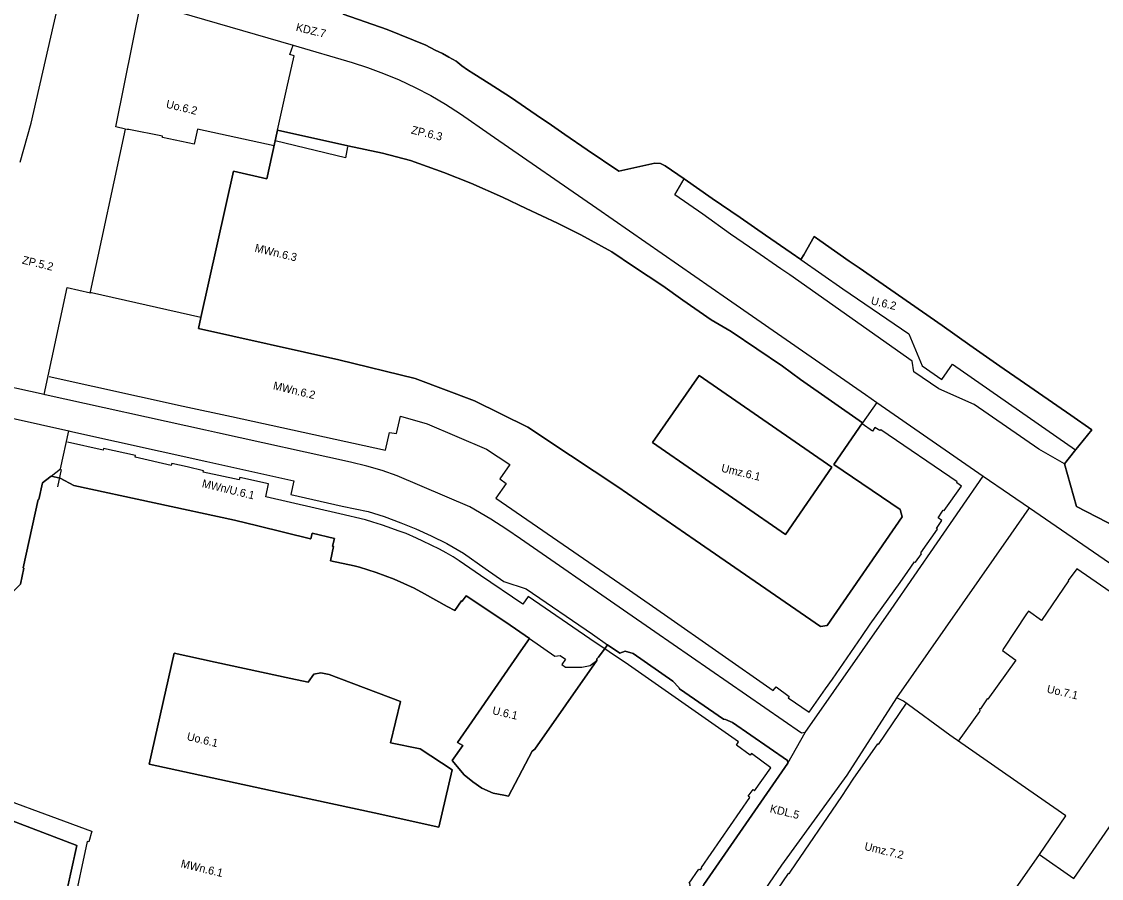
# Model space of a CAD drawing. Extents: x 7429686 to 7432896, y 5547954 to 5550600.
# Drawn here: x 7431331 to 7431871, y 5549657 to 5550085 of the extents above; entities that cross this region are included whole.
import ezdxf

# ---------------------------------------------------------------- set-up
doc = ezdxf.new("R2010")
doc.units = 0
for name, color, linetype in [('granica planu', 7, 'Continuous'), ('linie rozgraniczające', 7, 'Continuous'), ('nieprzekraczalna linia zabudowy', 7, 'Continuous'), ('obowiązująca linia zabudowy', 7, 'Continuous'), ('oznaczenia przeznaczeń', 7, 'Continuous')]:
    doc.layers.add(name, color=color, linetype=linetype)

msp = doc.modelspace()

# ---------------------------------------------------------------- linework, layer by layer
at = {"layer": 'granica planu'}
msp.add_lwpolyline([(7431492.16, 5550088.86), (7431514.08, 5550081.13), (7431533.41, 5550073.41), (7431538.07, 5550070.86), (7431541.78, 5550069.16), (7431544.95, 5550067.39), (7431548.55, 5550065.42), (7431549.45, 5550064.68), (7431551.38, 5550063.11), (7431554.34, 5550061.11), (7431557.5, 5550059.12), (7431565.17, 5550054.17), (7431575.82, 5550047.31), (7431588.58, 5550038.53), (7431596.17, 5550033.34), (7431602.99, 5550028.7), (7431614.12, 5550021.1), (7431629.82, 5550010.4), (7431647.84, 5550014.36), (7431650.74, 5550014.23), (7431653.1, 5550013.01), (7431662.53, 5550006.51), (7431676.53, 5549996.85), (7431690.53, 5549987.2), (7431703.2, 5549978.48), (7431716.01, 5549969.64), (7431720.86, 5549966.3), (7431722.24, 5549968.65), (7431727.56, 5549977.72), (7431730.29, 5549975.84), (7431745.04, 5549965.53), (7431749.96, 5549962.11), (7431791.39, 5549933.25), (7431805.34, 5549923.53), (7431820.33, 5549913.08), (7431822.49, 5549911.58), (7431830.37, 5549906.09), (7431855.65, 5549888.47), (7431866.16, 5549881.15), (7431857.58, 5549870.55), (7431852.56, 5549864.15), (7431858.59, 5549842.92), (7431955.59, 5549792.81)], dxfattribs=at)
at = {"layer": 'linie rozgraniczające'}
for p, q in [((7431459.36, 5550030.98), (7431453.98, 5550006.65)), ((7431494.51, 5550023.03), (7431459.36, 5550030.98)), ((7431511.89, 5550019.45), (7431494.51, 5550023.03)), ((7431525.8, 5550015.74), (7431511.89, 5550019.45)), ((7431542.43, 5550009.76), (7431525.8, 5550015.74)), ((7431556, 5550004.5), (7431542.43, 5550009.76)), ((7431571.74, 5549997.36), (7431556, 5550004.5)), ((7431583.66, 5549991.85), (7431571.74, 5549997.36)), ((7431599.28, 5549984.47), (7431583.66, 5549991.85)), ((7431610.82, 5549978.54), (7431599.28, 5549984.47)), ((7431626.4, 5549970.11), (7431610.82, 5549978.54)), ((7431637.21, 5549962.76), (7431626.4, 5549970.11)), ((7431651.88, 5549953.12), (7431637.21, 5549962.76)), ((7431661.83, 5549945.98), (7431651.88, 5549953.12)), ((7431676.03, 5549936.21), (7431661.83, 5549945.98)), ((7431686.08, 5549930.37), (7431676.03, 5549936.21)), ((7431711.66, 5549913.01), (7431686.08, 5549930.37)), ((7431720.63, 5549906.35), (7431711.66, 5549913.01)), ((7431736.35, 5549862.5), (7431670.09, 5549908.37)), ((7431670.09, 5549908.37), (7431736.35, 5549862.5)), ((7431751.68, 5549884.66), (7431720.63, 5549906.35)), ((7431557.81, 5549895.77), (7431584.5, 5549882.55)), ((7431737.32, 5549863.9), (7431751.68, 5549884.66)), ((7431713.11, 5549828.92), (7431736.35, 5549862.5)), ((7431736.35, 5549862.5), (7431713.11, 5549828.92)), ((7431770.41, 5549841.48), (7431737.32, 5549863.9)), ((7431341.93, 5549854.71), (7431340.14, 5549846.42)), ((7431345.63, 5549857.59), (7431341.93, 5549854.71)), ((7431346.28, 5549858.1), (7431345.63, 5549857.59)), ((7431629.36, 5549852.79), (7431668.05, 5549826.1)), ((7431339.7, 5549846.45), (7431332.2, 5549812.2)), ((7431340.14, 5549846.42), (7431339.7, 5549846.45)), ((7431771.49, 5549837.73), (7431770.41, 5549841.48)), ((7431476.68, 5549829.61), (7431476.17, 5549827.35)), ((7431487.81, 5549826.91), (7431476.68, 5549829.61)), ((7431485.75, 5549815.81), (7431487.35, 5549822.97)), ((7431668.05, 5549826.1), (7431730.64, 5549782.92)), ((7431332.59, 5549812.04), (7431330.89, 5549804.16)), ((7431332.2, 5549812.2), (7431332.59, 5549812.04)), ((7431585.18, 5549776.95), (7431573.48, 5549785.17)), ((7431618.88, 5549765.93), (7431587.91, 5549721.73)), ((7431546.55, 5549711.43), (7431530.66, 5549721.85)), ((7431530.66, 5549721.85), (7431546.55, 5549711.43)), ((7431672.28, 5549654.05), (7431714.41, 5549714.66)), ((7431300.13, 5549695.97), (7431359.15, 5549673.6)), ((7431359.15, 5549673.6), (7431350.69, 5549635.72))]:
    msp.add_line(p, q, dxfattribs=at)
for points in [[(7431336.35, 5550034.33), (7431351.87, 5550103.07)], [(7431378.63, 5550032.55), (7431391.27, 5550095.33)], [(7431391.27, 5550095.33), (7431467.17, 5550073.29)], [(7431662.53, 5550006.51), (7431653.1, 5550013.01), (7431650.74, 5550014.23), (7431647.84, 5550014.36), (7431629.82, 5550010.4), (7431614.12, 5550021.1), (7431602.99, 5550028.7), (7431596.17, 5550033.34), (7431588.58, 5550038.53), (7431575.82, 5550047.31), (7431565.17, 5550054.17), (7431557.5, 5550059.12), (7431554.34, 5550061.11), (7431551.38, 5550063.11), (7431549.45, 5550064.68), (7431548.55, 5550065.42), (7431544.95, 5550067.39), (7431541.78, 5550069.16), (7431538.07, 5550070.86), (7431533.41, 5550073.41), (7431514.08, 5550081.13), (7431492.16, 5550088.86)], [(7431465.55, 5550068.63), (7431467.17, 5550073.29)], [(7431467.17, 5550073.29), (7431496.63, 5550064.73)], [(7431463.98, 5550051.88), (7431467.59, 5550068.09)], [(7431467.59, 5550068.09), (7431465.55, 5550068.63)], [(7431496.63, 5550064.73), (7431504.34, 5550062.24)], [(7431504.34, 5550062.24), (7431512.37, 5550059.22)], [(7431512.37, 5550059.22), (7431520.14, 5550056.01)], [(7431520.14, 5550056.01), (7431528.16, 5550052.26)], [(7431459.66, 5550032.33), (7431463.98, 5550051.88)], [(7431528.16, 5550052.26), (7431535.91, 5550048.26)], [(7431535.91, 5550048.26), (7431543.34, 5550043.87)], [(7431543.34, 5550043.87), (7431550.72, 5550039.02)], [(7431550.72, 5550039.02), (7431565.67, 5550028.68)], [(7431330.83, 5550014.86), (7431336.35, 5550034.33)], [(7431365.98, 5549950.18), (7431383.4, 5550031.42)], [(7431383.4, 5550031.42), (7431378.63, 5550032.55)], [(7431459.36, 5550030.98), (7431459.66, 5550032.33)], [(7431421.01, 5549937.29), (7431437.36, 5550010.38), (7431453.98, 5550006.65), (7431459.36, 5550030.98)], [(7431459.36, 5550030.98), (7431494.51, 5550023.03), (7431511.89, 5550019.45), (7431525.8, 5550015.74), (7431542.43, 5550009.76), (7431556, 5550004.5), (7431571.74, 5549997.36), (7431583.66, 5549991.85), (7431599.28, 5549984.47), (7431610.82, 5549978.54), (7431626.4, 5549970.11), (7431637.21, 5549962.76), (7431651.88, 5549953.12), (7431661.83, 5549945.98), (7431676.03, 5549936.21), (7431686.08, 5549930.37), (7431711.66, 5549913.01), (7431720.63, 5549906.35), (7431751.68, 5549884.66)], [(7431565.67, 5550028.68), (7431567.72, 5550027.26)], [(7431567.72, 5550027.26), (7431618.83, 5549991.92)], [(7431453.98, 5550006.65), (7431437.36, 5550010.38), (7431421.01, 5549937.29)], [(7431657.92, 5549998.63), (7431662.53, 5550006.51)], [(7431852.56, 5549864.15), (7431857.58, 5549870.55), (7431866.16, 5549881.15), (7431855.65, 5549888.47), (7431830.37, 5549906.09), (7431822.49, 5549911.58), (7431820.33, 5549913.08), (7431805.34, 5549923.53), (7431791.39, 5549933.25), (7431749.96, 5549962.11), (7431745.04, 5549965.53), (7431730.29, 5549975.84), (7431727.56, 5549977.72), (7431722.24, 5549968.65), (7431720.86, 5549966.3), (7431716.01, 5549969.64), (7431703.2, 5549978.48), (7431690.53, 5549987.2), (7431676.53, 5549996.85), (7431662.53, 5550006.51)], [(7431671.92, 5549988.91), (7431657.92, 5549998.63)], [(7431618.83, 5549991.92), (7431684.1, 5549946.63)], [(7431685.75, 5549978.97), (7431671.92, 5549988.91)], [(7431698.41, 5549970.24), (7431685.75, 5549978.97)], [(7431710.77, 5549961.71), (7431698.41, 5549970.24)], [(7431715.3, 5549958.58), (7431710.77, 5549961.71)], [(7431776.51, 5549915.59), (7431715.3, 5549958.58)], [(7431342.73, 5549898.88), (7431354.21, 5549952.32)], [(7431354.21, 5549952.32), (7431365.87, 5549949.69)], [(7431365.87, 5549949.69), (7431365.98, 5549950.18)], [(7431366.36, 5549949.58), (7431365.87, 5549949.69)], [(7431421.01, 5549937.29), (7431366.36, 5549949.58)], [(7431684.1, 5549946.63), (7431753.19, 5549898.78)], [(7431421.01, 5549937.29), (7431419.81, 5549931.9), (7431490.03, 5549916.19), (7431528.06, 5549906.78), (7431557.81, 5549895.77)], [(7431751.68, 5549884.66), (7431737.32, 5549863.9), (7431770.41, 5549841.48), (7431771.49, 5549837.73), (7431734.02, 5549783.54), (7431730.64, 5549782.92), (7431668.05, 5549826.1), (7431629.36, 5549852.79), (7431605.72, 5549868.47), (7431584.5, 5549882.55), (7431557.81, 5549895.77), (7431528.06, 5549906.78), (7431490.03, 5549916.19), (7431419.81, 5549931.9), (7431421.01, 5549937.29)], [(7431777.3, 5549910.17), (7431776.51, 5549915.59)], [(7431670.09, 5549908.37), (7431646.77, 5549874.81), (7431713.11, 5549828.92)], [(7431713.11, 5549828.92), (7431646.77, 5549874.81), (7431670.09, 5549908.37)], [(7431789.82, 5549901.66), (7431777.3, 5549910.17)], [(7431342.73, 5549898.88), (7431313.84, 5549905.24)], [(7431343.22, 5549898.77), (7431342.73, 5549898.88)], [(7431423.43, 5549881.09), (7431343.22, 5549898.77)], [(7431753.19, 5549898.78), (7431758.77, 5549894.91)], [(7431807.42, 5549893.93), (7431789.82, 5549901.66)], [(7431758.77, 5549894.91), (7431751.68, 5549884.66)], [(7431758.77, 5549894.91), (7431811.93, 5549858.1)], [(7431839.81, 5549871.57), (7431807.42, 5549893.93)], [(7431326.76, 5549886.99), (7431355.15, 5549880.69)], [(7431350.84, 5549861.65), (7431355.15, 5549880.69)], [(7431355.15, 5549880.69), (7431355.64, 5549880.58)], [(7431355.64, 5549880.58), (7431424.06, 5549865.4)], [(7431429.36, 5549879.77), (7431423.43, 5549881.09)], [(7431584.5, 5549882.55), (7431605.72, 5549868.47), (7431629.36, 5549852.79)], [(7431495.74, 5549865.02), (7431429.36, 5549879.77)], [(7431852.56, 5549864.15), (7431839.81, 5549871.57)], [(7431424.06, 5549865.4), (7431467.44, 5549855.77)], [(7431504.02, 5549863.03), (7431495.74, 5549865.02)], [(7432170.68, 5549349.73), (7432101.09, 5549524.55), (7432091.7, 5549548.15), (7432088.5, 5549556.18), (7432087.92, 5549566.51), (7432064.55, 5549625.33), (7432059.26, 5549630.41), (7432025.13, 5549714.87), (7432023.35, 5549718.94), (7432016.93, 5549731.12), (7432011.47, 5549739.51), (7432005.61, 5549747.16), (7432002.88, 5549750.78), (7431999.04, 5549755.42), (7431989.27, 5549765.25), (7431986.1, 5549768.47), (7431982.62, 5549771.59), (7431983.7, 5549773.53), (7431976.11, 5549778.51), (7431955.59, 5549792.81), (7431858.59, 5549842.92), (7431852.56, 5549864.15)], [(7431852.56, 5549864.15), (7431852.86, 5549863.94), (7431852.56, 5549864.15)], [(7431346.28, 5549858.1), (7431350.84, 5549861.65)], [(7431511.6, 5549860.85), (7431504.02, 5549863.03)], [(7431519.18, 5549858.29), (7431511.6, 5549860.85)], [(7431350.69, 5549635.72), (7431359.15, 5549673.6), (7431300.13, 5549695.97), (7431299.66, 5549696.15), (7431304.47, 5549715.98), (7431303.72, 5549721.28), (7431319.02, 5549792.1), (7431330.89, 5549804.16), (7431332.59, 5549812.04), (7431332.2, 5549812.2), (7431339.7, 5549846.45), (7431340.14, 5549846.42), (7431341.93, 5549854.71), (7431345.63, 5549857.59), (7431346.28, 5549858.1)], [(7431437.93, 5549836.03), (7431357.58, 5549853.37), (7431350.76, 5549857), (7431346.28, 5549858.1)], [(7431346.28, 5549858.1), (7431350.76, 5549857)], [(7431350.76, 5549857), (7431357.58, 5549853.37), (7431437.93, 5549836.03), (7431449.6, 5549833.19), (7431475.75, 5549826.73), (7431476.03, 5549826.75), (7431476.17, 5549827.35), (7431476.68, 5549829.61), (7431487.81, 5549826.91), (7431486.89, 5549823.12), (7431487.35, 5549822.97), (7431485.75, 5549815.81), (7431497.62, 5549813.34), (7431500.27, 5549812.65), (7431508.56, 5549810), (7431517.56, 5549806.66), (7431522.52, 5549804.51), (7431527.58, 5549802.12), (7431532.84, 5549799.31), (7431544.18, 5549793.03), (7431547.99, 5549790.93), (7431551.3, 5549795.76), (7431551.57, 5549795.55), (7431553.59, 5549798.37), (7431573.48, 5549785.17), (7431585.18, 5549776.95)], [(7431467.44, 5549855.77), (7431465.99, 5549848.95)], [(7431555.36, 5549842.69), (7431519.18, 5549858.29)], [(7431765.93, 5549791.51), (7431811.93, 5549858.1)], [(7431811.93, 5549858.1), (7431825.03, 5549849.08)], [(7431465.99, 5549848.95), (7431491.59, 5549843.16)], [(7431825.03, 5549849.08), (7431835.02, 5549842.19)], [(7431491.59, 5549843.16), (7431504.71, 5549840.39)], [(7431565.99, 5549836.57), (7431555.36, 5549842.69)], [(7431504.71, 5549840.39), (7431512.58, 5549837.85)], [(7431512.58, 5549837.85), (7431521.04, 5549834.69)], [(7431730.64, 5549782.92), (7431734.02, 5549783.54), (7431771.49, 5549837.73)], [(7431825.84, 5549829.03), (7431835.02, 5549842.19)], [(7431835.02, 5549842.19), (7431909.67, 5549790.95)], [(7431475.75, 5549826.73), (7431449.6, 5549833.19), (7431437.93, 5549836.03)], [(7431521.04, 5549834.69), (7431528.54, 5549831.84)], [(7431528.54, 5549831.84), (7431536.13, 5549828.29)], [(7431573.92, 5549831.42), (7431565.99, 5549836.57)], [(7431476.17, 5549827.35), (7431476.03, 5549826.75), (7431475.75, 5549826.73)], [(7431487.35, 5549822.97), (7431486.89, 5549823.12), (7431487.81, 5549826.91)], [(7431536.13, 5549828.29), (7431543.87, 5549824.47)], [(7431580.71, 5549826.82), (7431573.92, 5549831.42)], [(7431632.21, 5549791.17), (7431580.71, 5549826.82)], [(7431768.82, 5549747.29), (7431825.84, 5549829.03)], [(7431543.87, 5549824.47), (7431552.21, 5549819.67)], [(7431547.99, 5549790.93), (7431544.18, 5549793.03), (7431532.84, 5549799.31), (7431527.58, 5549802.12), (7431522.52, 5549804.51), (7431517.56, 5549806.66), (7431508.56, 5549810), (7431500.27, 5549812.65), (7431497.62, 5549813.34), (7431485.75, 5549815.81)], [(7431552.21, 5549819.67), (7431563.17, 5549811.87)], [(7431563.17, 5549811.87), (7431572.44, 5549805.5)], [(7431572.44, 5549805.5), (7431583.57, 5549801.81)], [(7431583.57, 5549801.81), (7431616.69, 5549779.06)], [(7431573.48, 5549785.17), (7431553.59, 5549798.37), (7431551.57, 5549795.55), (7431551.3, 5549795.76), (7431547.99, 5549790.93)], [(7431647.91, 5549780.33), (7431632.21, 5549791.17)], [(7431722.99, 5549729.95), (7431765.93, 5549791.51)], [(7431616.69, 5549779.06), (7431624.25, 5549773.87)], [(7431721.19, 5549729.73), (7431647.91, 5549780.33)], [(7431587.91, 5549721.73), (7431586.57, 5549720.77), (7431574.74, 5549698.23), (7431572.4, 5549698.71), (7431567.13, 5549699.77), (7431561.52, 5549702.15), (7431556.93, 5549705.45), (7431552.68, 5549708.93), (7431546.69, 5549715.97), (7431551.91, 5549723.46), (7431549.29, 5549725.1), (7431556.41, 5549735.38), (7431580.91, 5549770.78), (7431585.18, 5549776.95)], [(7431585.18, 5549776.95), (7431580.91, 5549770.78), (7431556.41, 5549735.38), (7431549.29, 5549725.1), (7431551.91, 5549723.46), (7431546.69, 5549715.97), (7431552.68, 5549708.93), (7431556.93, 5549705.45), (7431561.52, 5549702.15), (7431567.13, 5549699.77), (7431572.4, 5549698.71), (7431574.74, 5549698.23), (7431586.57, 5549720.77), (7431587.91, 5549721.73), (7431618.88, 5549765.93)], [(7431585.18, 5549776.95), (7431597.9, 5549768.22)], [(7431624.25, 5549773.87), (7431624.17, 5549773.73), (7431623.85, 5549773.29), (7431623.09, 5549772.2), (7431619.69, 5549767.66), (7431618.97, 5549766.76), (7431618.88, 5549765.93)], [(7431618.88, 5549765.93), (7431618.97, 5549766.76), (7431619.69, 5549767.66), (7431623.09, 5549772.2), (7431623.85, 5549773.29), (7431624.17, 5549773.73), (7431624.25, 5549773.87)], [(7431714.41, 5549714.66), (7431714.08, 5549716.09), (7431686.7, 5549735.01), (7431683.14, 5549736.44), (7431682.15, 5549736.64), (7431660.17, 5549751.85), (7431659.91, 5549752.51), (7431656.94, 5549755.74), (7431636.98, 5549769.52), (7431633.08, 5549770.6), (7431630.31, 5549769.71), (7431624.25, 5549773.87)], [(7431624.25, 5549773.87), (7431630.31, 5549769.71), (7431633.08, 5549770.6), (7431636.98, 5549769.52), (7431656.94, 5549755.74), (7431659.91, 5549752.51), (7431660.17, 5549751.85), (7431682.15, 5549736.64), (7431683.14, 5549736.44), (7431686.7, 5549735.01), (7431714.08, 5549716.09), (7431714.41, 5549714.66)], [(7431466.06, 5549756.95), (7431428.13, 5549765.21), (7431407.72, 5549769.64), (7431395.27, 5549714.12), (7431430.51, 5549706.51)], [(7431430.51, 5549706.51), (7431395.27, 5549714.12), (7431407.72, 5549769.64), (7431428.13, 5549765.21), (7431466.06, 5549756.95)], [(7431597.9, 5549768.22), (7431600.54, 5549768.51)], [(7431600.54, 5549768.51), (7431603.2, 5549766.62)], [(7431603.2, 5549766.62), (7431601.39, 5549763.97)], [(7431601.39, 5549763.97), (7431603.2, 5549762.72)], [(7431603.2, 5549762.72), (7431611.45, 5549762.68)], [(7431611.45, 5549762.68), (7431615.54, 5549763.57)], [(7431615.54, 5549763.57), (7431618.88, 5549765.93)], [(7431481.01, 5549759.79), (7431477.45, 5549759.15), (7431474.69, 5549755.11), (7431466.06, 5549756.95)], [(7431466.06, 5549756.95), (7431474.69, 5549755.11), (7431477.45, 5549759.15), (7431481.01, 5549759.79)], [(7431520.78, 5549745.44), (7431485.1, 5549758.97), (7431481.01, 5549759.79)], [(7431481.01, 5549759.79), (7431485.1, 5549758.97), (7431520.78, 5549745.44)], [(7431530.66, 5549721.85), (7431515.87, 5549724.94), (7431520.78, 5549745.44)], [(7431520.78, 5549745.44), (7431515.87, 5549724.94), (7431530.66, 5549721.85)], [(7431743.89, 5549708.77), (7431768.82, 5549747.29)], [(7431772.04, 5549745.59), (7431768.82, 5549747.29)], [(7431795.22, 5549728.61), (7431772.04, 5549745.59)], [(7431714.41, 5549714.66), (7431722.99, 5549729.95)], [(7431722.99, 5549729.95), (7431721.19, 5549729.73)], [(7431830.92, 5549703.83), (7431795.22, 5549728.61)], [(7431714.41, 5549714.66), (7431672.28, 5549654.05), (7431628.07, 5549590.29)], [(7431507.64, 5549689.91), (7431539.9, 5549682.72), (7431546.55, 5549711.43)], [(7431546.55, 5549711.43), (7431539.9, 5549682.72), (7431507.64, 5549689.91)], [(7431711.33, 5549663.7), (7431743.89, 5549708.77)], [(7431430.51, 5549706.51), (7431455.86, 5549701.04), (7431507.64, 5549689.91)], [(7431507.64, 5549689.91), (7431455.86, 5549701.04), (7431430.51, 5549706.51)], [(7431853.17, 5549688.38), (7431830.92, 5549703.83)], [(7431840.13, 5549669.13), (7431853.17, 5549688.38)], [(7431857.23, 5549657.14), (7431876.16, 5549684.59)], [(7431832.75, 5549658.62), (7431840.13, 5549669.13)], [(7431840.13, 5549669.13), (7431857.23, 5549657.14)], [(7431696.82, 5549642.68), (7431711.33, 5549663.7)], [(7431815.03, 5549633.4), (7431832.75, 5549658.62)]]:
    msp.add_lwpolyline(points, dxfattribs=at)
at = {"layer": 'nieprzekraczalna linia zabudowy'}
msp.add_lwpolyline([(7431720.86, 5549966.3), (7431741.83, 5549951.57), (7431774.75, 5549929.24), (7431781.37, 5549913.26), (7431791.26, 5549906.37), (7431796.58, 5549914), (7431858.08, 5549871.2)], dxfattribs=at)
at = {"layer": 'obowiązująca linia zabudowy'}
for p, q in [((7431493.36, 5550017.13), (7431458.16, 5550025.53)), ((7431520.72, 5549888.01), (7431534.1, 5549884.19))]:
    msp.add_line(p, q, dxfattribs=at)
for points in [[(7431457.6, 5550023.01), (7431419.45, 5550031.47), (7431417.79, 5550023.92), (7431401.81, 5550027.22), (7431401.89, 5550027.94), (7431385.01, 5550031.2), (7431383.89, 5550031.31)], [(7431494.4, 5550022.54), (7431493.36, 5550017.13)], [(7431345.18, 5549907.92), (7431412.29, 5549892.96), (7431436.32, 5549887.84), (7431513.36, 5549871.12), (7431515.35, 5549879.94), (7431518.75, 5549879.39), (7431520.72, 5549888.01)], [(7431534.1, 5549884.19), (7431563.73, 5549871.56), (7431575.48, 5549863.89)], [(7431724.95, 5549740.15), (7431733.07, 5549751.86), (7431736.67, 5549756.71), (7431751.35, 5549778.02), (7431755.53, 5549784.1), (7431770.39, 5549804.87), (7431774.33, 5549810.5), (7431777.68, 5549815.27), (7431778.19, 5549815.03), (7431781.19, 5549819.28), (7431780.82, 5549819.72), (7431789.05, 5549831.59), (7431788.58, 5549831.98), (7431791.19, 5549835.85), (7431789.36, 5549837.23), (7431791.55, 5549840.6), (7431791.88, 5549841.11), (7431792.52, 5549840.89), (7431801.03, 5549853.04), (7431798.8, 5549854.71), (7431799, 5549855.18), (7431760.72, 5549881.23), (7431760.32, 5549880.84), (7431757.81, 5549882.33), (7431756.66, 5549880.57)], [(7431756.66, 5549880.57), (7431751.39, 5549884.25)], [(7431581.96, 5549794.13), (7431560.83, 5549808.47), (7431550.13, 5549815.79), (7431547.19, 5549817.73), (7431543.67, 5549819.75), (7431540.27, 5549821.66), (7431531.9, 5549825.67), (7431528.77, 5549827.03), (7431523.65, 5549829.41), (7431519.56, 5549830.79), (7431514.6, 5549832.6), (7431511.38, 5549833.76), (7431507.04, 5549835.13), (7431503.27, 5549836.17), (7431490.54, 5549839.18), (7431453.45, 5549847.76), (7431454.92, 5549854.2), (7431440.46, 5549857.46), (7431440.15, 5549856.29), (7431422.27, 5549860.1), (7431422.35, 5549860.81), (7431414.25, 5549862.67), (7431406.58, 5549864.43), (7431406.29, 5549863.4), (7431388.17, 5549867.59), (7431388.33, 5549868.32), (7431372.41, 5549871.88), (7431372.18, 5549871.08), (7431354.37, 5549874.98)], [(7431351.29, 5549861.36), (7431349.35, 5549852.78)], [(7431575.48, 5549863.89), (7431570.5, 5549856.77), (7431573.62, 5549854.45), (7431568.49, 5549847.09), (7431633.08, 5549802.58), (7431652.76, 5549788.97), (7431707.01, 5549750.93), (7431708.57, 5549752.81), (7431715.05, 5549748.04), (7431714.55, 5549747.39), (7431724.95, 5549740.15)], [(7431928.02, 5549763.97), (7431858.73, 5549811.79), (7431854.37, 5549805.94), (7431854.59, 5549805.72), (7431841.11, 5549785.99), (7431834.5, 5549790.63), (7431833.55, 5549789.27), (7431822.3, 5549772.2), (7431821.52, 5549771.01), (7431828.18, 5549766.14), (7431814.32, 5549746.66), (7431814, 5549746.83), (7431810.53, 5549741.85), (7431810.07, 5549741.88), (7431810.26, 5549741.04), (7431810.05, 5549740.59), (7431799.46, 5549725.67)], [(7431626.8, 5549597.76), (7431664.36, 5549652.68), (7431664.8, 5549652.45), (7431665.74, 5549653.73), (7431665.43, 5549654), (7431665.61, 5549654.29), (7431664.99, 5549654.7), (7431669.82, 5549661.81), (7431670.71, 5549661.35), (7431671.43, 5549662.38), (7431671.11, 5549662.66), (7431695.3, 5549697.49), (7431694.49, 5549698.23), (7431696.94, 5549701.47), (7431697.66, 5549700.93), (7431705.8, 5549712.45), (7431696.2, 5549719.48), (7431695.58, 5549718.78), (7431688.71, 5549723.66), (7431689.69, 5549725.42), (7431634.7, 5549763.77), (7431615.39, 5549776.81), (7431584.64, 5549797.95), (7431581.96, 5549794.13)], [(7431773.4, 5549744.6), (7431759.38, 5549724.04), (7431759.07, 5549724.28), (7431746.83, 5549706.73), (7431741.13, 5549698.11), (7431715.67, 5549660.69), (7431714.76, 5549659.38), (7431714.47, 5549659.55), (7431701.27, 5549640.26), (7431693.49, 5549628.9), (7431657.59, 5549576.7)], [(7431302.17, 5549704.38), (7431366.43, 5549680.74), (7431366.53, 5549680.72), (7431365.08, 5549675.38), (7431364.29, 5549675.54), (7431357.35, 5549643.62)]]:
    msp.add_lwpolyline(points, dxfattribs=at)

# ---------------------------------------------------------------- texts
at = {"layer": 'oznaczenia przeznaczeń'}
for s, rotation, p in [('KDZ.7', 346.4891, (7431468.28, 5550080.58)), ('Uo.6.2', 346.4891, (7431403.38, 5550042.2)), ('ZP.6.3', 346.4891, (7431525.88, 5550029.27)), ('MWn.6.3', 346.5122, (7431447.69, 5549970.3)), ('ZP.5.2', 346.4891, (7431331.46, 5549964.3)), ('U.6.2', 346.4891, (7431755.54, 5549944)), ('MWn.6.2', 346.4891, (7431456.87, 5549901.53)), ('Umz.6.1', 346.4891, (7431680.78, 5549860.37)), ('MWn/U.6.1', 346.4891, (7431421.34, 5549852.67)), ('Uo.7.1', 347.0609, (7431843.48, 5549750.02)), ('U.6.1', 347.0609, (7431566.42, 5549739.24)), ('Uo.6.1', 346.4891, (7431413.79, 5549726.32)), ('KDL.5', 346.4891, (7431705.08, 5549690.22)), ('Umz.7.2', 346.4891, (7431752.32, 5549671.41)), ('MWn.6.1', 346.4891, (7431410.75, 5549662.77))]:
    msp.add_text(s, height=4, rotation=rotation, dxfattribs=at).set_placement(p)

doc.saveas('drawing.dxf')
